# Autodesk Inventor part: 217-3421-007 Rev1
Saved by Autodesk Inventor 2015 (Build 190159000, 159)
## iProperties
Created: 2014-11
Part Number: 217-3421-007 Rev1
Material: Generic
Document SubType Name: Modeling
Designer: User
Density: 1 g/cm^3
Appearance: Default
Author: User
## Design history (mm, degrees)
node "217-3421-007 Rev1.ipt1"
node "Cut-Extrude2"
node "Base1"
